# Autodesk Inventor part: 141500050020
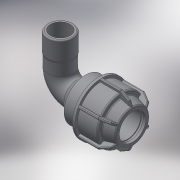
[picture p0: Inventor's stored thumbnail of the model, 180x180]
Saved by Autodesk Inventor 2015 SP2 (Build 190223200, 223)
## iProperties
Created: 2017-08
Part Number: 141500050020
Material: Generic
Description: L.14 90° ELBOW FEMALE ADAPTOR (SILVER) 50-2"
Document SubType Name: Modeling
Designer: KIM
Density: 1 g/cm^3
Appearance: Default
Author: KIM
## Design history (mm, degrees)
derived "141500.ipt"
feature "Solid1::141500.ipt"
feature "Solid2::141500.ipt"
tag "TaggingFeature1"
body "Solid1"
body "Solid2"
other parameters: "d2" = 74, "d4" = 15 deg, "d5" = 48.84, "d6" = 16.1172, "d10" = 92, "d16" = 51, "d17" = 3.7, "d24" = 3.7, "d25" = 82.8, "d26" = 69, "d27" = 3.7, "d28" = 135 deg, "d29" = 2.22, "d31" = 2.5, "d46" = 150 deg, "d49" = 4.6, "d50" = 0, "d58" = 1.5, "d61" = 360 deg, "d63" = 45, "d94" = 79, "d95" = 56.656, "d96" = 73.6528, "d98" = 45.3248, "d99" = 66.28752, "d100" = 135 deg, "d108" = 2.5, "d112" = 39, "d113" = 102, "d114" = 75.48, "d115" = 66.28752, "d116" = 45 deg, "d117" = 0, "d118" = 0, "G_" = 56.656, "E_" = 92, "A_" = 102, "l_" = 74, "A_1" = 79
